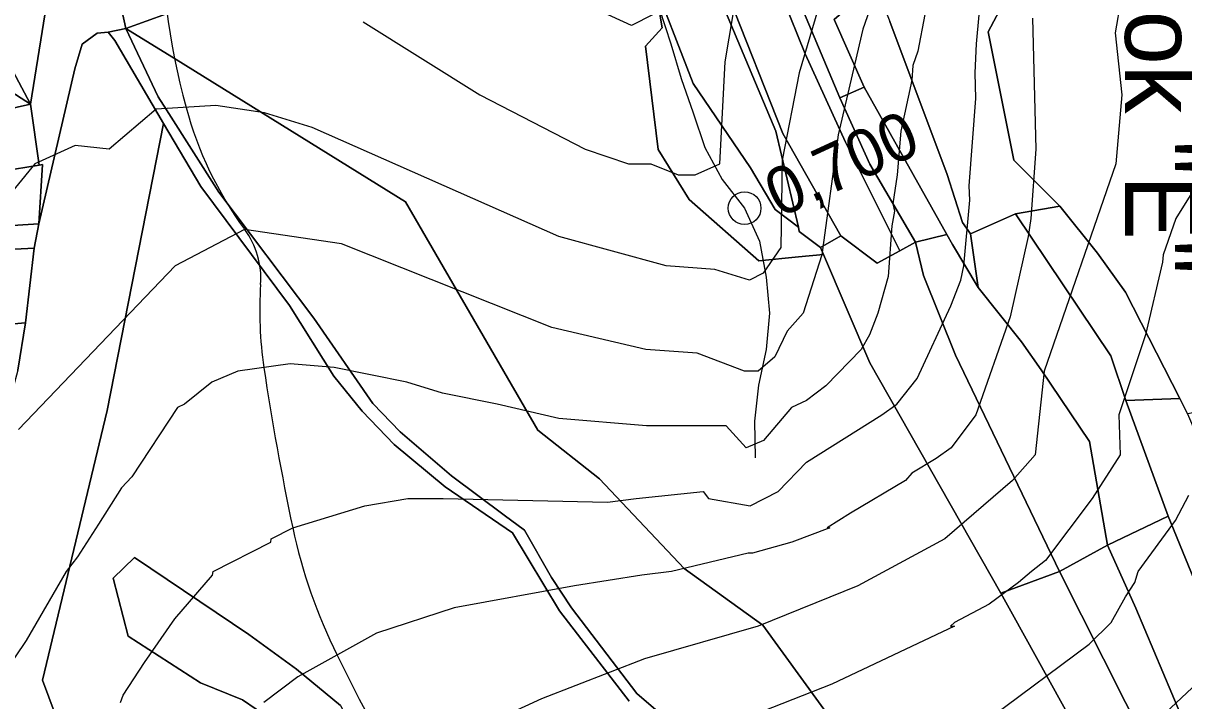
# Model space of a CAD drawing. Extents: x -510989 to -501240, y -1184665 to -1176098.
# Drawn here: x -504613.7 to -504294.9, y -1182831.5 to -1182645.4 of the extents above; entities that cross this region are included whole.
import ezdxf

# ---------------------------------------------------------------- set-up
doc = ezdxf.new("R2010")
doc.units = 0
for name, color, linetype in [('lesni_pozemek', 7, 'Continuous'), ('NAVRH_rozvodnice', 7, 'Continuous'), ('orna_puda', 7, 'Continuous'), ('ostatni_plocha_x_neplodna_puda', 7, 'Continuous'), ('ostatni_plocha_x_ostatni_komunikace', 7, 'Continuous'), ('STAV_zaplavove_uzemi', 7, 'Continuous'), ('trasovani_toku', 7, 'Continuous'), ('trvaly_travni_porost', 7, 'Continuous'), ('vrstevnice_01', 7, 'Continuous'), ('vrstevnice_02', 7, 'Continuous')]:
    doc.layers.add(name, color=color, linetype=linetype)

msp = doc.modelspace()

# ---------------------------------------------------------------- linework, layer by layer
at = {"layer": 'lesni_pozemek'}
for points in [[(-504108.08, -1182644.43), (-504125.54, -1182629.68), (-504155.94, -1182673.32), (-504174.32, -1182695.83), (-504210.52, -1182722.69), (-504235.93, -1182738.25), (-504264.25, -1182747.48), (-504293.81, -1182752.72), (-504295.93, -1182748.47), (-504310.85, -1182719.26), (-504318.59, -1182708.58), (-504328.95, -1182695.62), (-504341.55, -1182683.01), (-504348.64, -1182647.73), (-504338.72, -1182629.02), (-504335.18, -1182603.23), (-504338, -1182582.37), (-504351.89, -1182548.22), (-504366.04, -1182490.92), (-504369.86, -1182481.57), (-504383.74, -1182456.35), (-504376.66, -1182443.95), (-504372.24, -1182440.22)], [(-504338.72, -1182629.02), (-504348.64, -1182647.73), (-504341.55, -1182683.01), (-504328.95, -1182695.62), (-504341.13, -1182697.77), (-504353.45, -1182703.22), (-504355.71, -1182700.13), (-504359.86, -1182686.91), (-504375.6, -1182644.92)], [(-504439.39, -1182639.55), (-504438.17, -1182646.67), (-504442.8, -1182651.66), (-504439.24, -1182680.04), (-504430.76, -1182693.84), (-504411.67, -1182710.63), (-504400.74, -1182709.57), (-504393.85, -1182708.89), (-504381.11, -1182738.71), (-504345.16, -1182801.96), (-504341.93, -1182807.78), (-504298.15, -1182886.77)], [(-504331.17, -1182920.13), (-504410.51, -1182810.8), (-504432.14, -1182795.22), (-504455.44, -1182770.6), (-504472.39, -1182757.22), (-504508.71, -1182694.47), (-504571.7, -1182655.37), (-504585.52, -1182646.79), (-504568.82, -1182640.74)], [(-504599.72, -1182849.21), (-504608.48, -1182825.92), (-504590.64, -1182751.76), (-504575.15, -1182672.92), (-504564.97, -1182690.25), (-504540.58, -1182722.93), (-504528.43, -1182742.33), (-504520.61, -1182752), (-504511.86, -1182761.09), (-504497.83, -1182772.71), (-504479.34, -1182785.43), (-504466.36, -1182806.8), (-504447.26, -1182831.66)], [(-504526.58, -1182832.88), (-504538.67, -1182822.87), (-504551.79, -1182813.34), (-504583.14, -1182792.17), (-504589, -1182797.83), (-504584.94, -1182813.82), (-504565.01, -1182826.65), (-504553.49, -1182831.27), (-504549.73, -1182833.84)]]:
    msp.add_lwpolyline(points, dxfattribs=at)
for points in [[(-504484.36, -1182553.26), (-504470.6, -1182583.61), (-504463.9, -1182605.8), (-504441.71, -1182630.91), (-504429.65, -1182661.94), (-504413.93, -1182685.1), (-504407.11, -1182696.55), (-504400.77, -1182701.43), (-504400.5, -1182702.56), (-504394.66, -1182707), (-504393.85, -1182708.89), (-504400.74, -1182709.57), (-504411.67, -1182710.63), (-504430.76, -1182693.84), (-504439.24, -1182680.04), (-504442.8, -1182651.66), (-504438.17, -1182646.67), (-504439.39, -1182639.55), (-504465.08, -1182614.54), (-504471.59, -1182602.62), (-504478.43, -1182596.87), (-504482.37, -1182589.69), (-504481.12, -1182577.4), (-504492.36, -1182555.2)], [(-504585.52, -1182646.79), (-504571.7, -1182655.37), (-504508.71, -1182694.47), (-504472.39, -1182757.22), (-504455.44, -1182770.6), (-504432.14, -1182795.22), (-504410.51, -1182810.8), (-504331.17, -1182920.13), (-504365.5, -1182891.46), (-504398.97, -1182869.17), (-504445.16, -1182829.52), (-504463.11, -1182806.05), (-504468.63, -1182797.64), (-504475.97, -1182784.67), (-504481.61, -1182780.53), (-504496.11, -1182769.71), (-504510.14, -1182757.63), (-504517.71, -1182749.85), (-504533.93, -1182726.38), (-504560, -1182691.8), (-504574.41, -1182669.14), (-504576.68, -1182665.56)], [(-504341.13, -1182697.77), (-504328.95, -1182695.62), (-504318.59, -1182708.58), (-504310.85, -1182719.26), (-504295.93, -1182748.47), (-504310.8, -1182749.04), (-504314.92, -1182736.74)], [(-504341.13, -1182697.77), (-504314.92, -1182736.74), (-504310.8, -1182749.04), (-504299.12, -1182780.84), (-504315.84, -1182788.78), (-504320.73, -1182760.26), (-504334.05, -1182740.56), (-504339.43, -1182732.91), (-504351.37, -1182717.96), (-504353.45, -1182703.22)], [(-504368.55, -1182705.56), (-504359.99, -1182703.4), (-504358.45, -1182706.15), (-504351.37, -1182717.96), (-504339.43, -1182732.91), (-504334.05, -1182740.56), (-504320.73, -1182760.26), (-504315.84, -1182788.78), (-504329.01, -1182796.01), (-504357.58, -1182736.53), (-504366.36, -1182714.7)], [(-504589, -1182797.83), (-504583.14, -1182792.17), (-504551.79, -1182813.34), (-504538.67, -1182822.87), (-504526.58, -1182832.88), (-504516.79, -1182851.72), (-504488.95, -1182890.19), (-504496.5, -1182892.54), (-504526.79, -1182855.38), (-504540.95, -1182840.36), (-504549.73, -1182833.84), (-504553.49, -1182831.27), (-504565.01, -1182826.65), (-504584.94, -1182813.82)]]:
    msp.add_lwpolyline(points, close=True, dxfattribs=at)
at = {"layer": 'NAVRH_rozvodnice'}
for centre, radius, start, end in [((-504365.5, -1182613.94), 210.69, 180.0167, 195.009), ((-504471.89, -1182642.46), 100.54, 195.009, 216.3106), ((-504571.39, -1182715.58), 22.94, 356.0559, 36.3106), ((-504442.83, -1182724.45), 105.93, 176.0559, 188.4422), ((-503829.42, -1182633.41), 726.05, 188.44219, 191.9708), ((-504395.61, -1182753.45), 147.28, 191.9708, 206.4269), ((-503520.82, -1182318.69), 1124.15, 206.42689, 210.10212)]:
    msp.add_arc(centre, radius, start, end, dxfattribs=at)
at = {"layer": 'orna_puda'}
for points in [[(-504628.48, -1182645.79), (-504618.4, -1182663.31), (-504611.77, -1182667.61), (-504642.34, -1182674.45), (-504667.79, -1182680.12), (-504671.74, -1182655.56)], [(-504642.34, -1182674.45), (-504611.77, -1182667.61), (-504609.38, -1182684.36), (-504639.94, -1182689.35)], [(-504664.63, -1182703.93), (-504609.45, -1182700.52), (-504610.7, -1182707.2), (-504663.97, -1182709.93)], [(-504662.47, -1182731.93), (-504613.08, -1182727.66), (-504615.26, -1182740.69), (-504617.46, -1182749.23), (-504620.21, -1182760.83), (-504659.96, -1182762.59)]]:
    msp.add_lwpolyline(points, close=True, dxfattribs=at)
at = {"layer": 'ostatni_plocha_x_neplodna_puda'}
msp.add_lwpolyline([(-504630.43, -1182488.04), (-504608.32, -1182618.85), (-504607.36, -1182640.23), (-504611.77, -1182667.61), (-504623.06, -1182646.35)], dxfattribs=at)
for points in [[(-504458.37, -1182546.96), (-504454.38, -1182543.14), (-504451.31, -1182553.99), (-504437.74, -1182594.84), (-504423.71, -1182628.8), (-504419.99, -1182637.8), (-504405.05, -1182675.65), (-504389.13, -1182703.75), (-504394.66, -1182707), (-504400.5, -1182702.56), (-504400.77, -1182701.43), (-504407, -1182675), (-504442.08, -1182591.33), (-504450.57, -1182563.65)], [(-504394.66, -1182707), (-504389.13, -1182703.75), (-504379.11, -1182711.25), (-504372.88, -1182707.9), (-504368.55, -1182705.56), (-504366.36, -1182714.7), (-504357.58, -1182736.53), (-504329.01, -1182796.01), (-504345.16, -1182801.96), (-504381.11, -1182738.71), (-504393.85, -1182708.89)]]:
    msp.add_lwpolyline(points, close=True, dxfattribs=at)
at = {"layer": 'ostatni_plocha_x_ostatni_komunikace'}
for points in [[(-504618.04, -1182497.86), (-504608.41, -1182541.97), (-504603.34, -1182565.18), (-504598.85, -1182585.72), (-504593.32, -1182611.07), (-504585.52, -1182646.79), (-504590.37, -1182647.84), (-504593.41, -1182648.12), (-504597.52, -1182651.15), (-504599.57, -1182657.86), (-504609.45, -1182700.52), (-504608.44, -1182684.21), (-504609.38, -1182684.36), (-504611.77, -1182667.61), (-504607.36, -1182640.23), (-504608.32, -1182618.85), (-504630.43, -1182488.04)], [(-504615.26, -1182740.69), (-504613.08, -1182727.66), (-504610.7, -1182707.2), (-504609.45, -1182700.52), (-504599.57, -1182657.86), (-504597.52, -1182651.15), (-504593.41, -1182648.12), (-504590.37, -1182647.84), (-504588.53, -1182650.14), (-504575.15, -1182672.92), (-504590.64, -1182751.76), (-504608.48, -1182825.92), (-504599.72, -1182849.21), (-504577.81, -1182854.21), (-504550.94, -1182892.74), (-504564.43, -1182890.78), (-504566.03, -1182890.55), (-504580.83, -1182865.24), (-504608.94, -1182852.85), (-504612.96, -1182855.54), (-504612.11, -1182873.57), (-504616.89, -1182868.86)], [(-504447.26, -1182831.66), (-504466.36, -1182806.8), (-504479.34, -1182785.43), (-504497.83, -1182772.71), (-504511.86, -1182761.09), (-504520.61, -1182752), (-504528.43, -1182742.33), (-504540.58, -1182722.93), (-504564.97, -1182690.25), (-504575.15, -1182672.92), (-504588.53, -1182650.14), (-504590.37, -1182647.84), (-504585.52, -1182646.79), (-504576.68, -1182665.56), (-504574.41, -1182669.14), (-504560, -1182691.8), (-504533.93, -1182726.38), (-504517.71, -1182749.85), (-504510.14, -1182757.63), (-504496.11, -1182769.71), (-504481.61, -1182780.53), (-504475.97, -1182784.67), (-504468.63, -1182797.64), (-504463.11, -1182806.05), (-504445.16, -1182829.52), (-504398.97, -1182869.17)]]:
    msp.add_lwpolyline(points, dxfattribs=at)
at = {"layer": 'STAV_zaplavove_uzemi'}
msp.add_spline([(-502250.32, -1184002.61), (-502355.07, -1183875.41), (-502442.37, -1183790.61), (-502477.29, -1183700.82), (-502532.16, -1183578.61), (-502567.08, -1183448.91), (-502626.05, -1183402.34), (-502705.41, -1183380.59), (-502814.2, -1183349.87), (-502882.03, -1183297.39), (-502931.95, -1183237.24), (-503042.02, -1183107.97), (-503139.64, -1183018.94), (-503222.14, -1182957.59), (-503308.56, -1182839.96), (-503316.24, -1182784.92), (-503330.32, -1182756.77), (-503348.24, -1182719.65), (-503334.16, -1182651.82), (-503323.92, -1182595.5), (-503313.68, -1182526.39), (-503294.1, -1182480.5), (-503251.86, -1182396.03), (-503229.34, -1182314.37), (-503216.1, -1182227.15), (-503242.43, -1182174.5), (-503271.86, -1182129.59), (-503287.34, -1182081.58), (-503343.88, -1182028.1), (-503361.79, -1182008.91), (-503396.35, -1181952.59), (-503442.43, -1181933.39), (-503497.46, -1181888.6), (-503525.62, -1181860.44), (-503528.18, -1181837.4), (-503548.66, -1181767.01), (-503558.9, -1181729.89), (-503576.82, -1181682.53), (-503578.1, -1181621.1), (-503567.86, -1181572.46), (-503552.5, -1181536.63), (-503538.04, -1181458.36), (-503518.33, -1181411.9), (-503509.88, -1181341.51), (-503497.21, -1181207.63), (-503499.77, -1181097.56), (-503498.02, -1181031.35), (-503510.82, -1180970.85), (-503549.22, -1180952.23), (-503571.32, -1180940.6), (-503605.07, -1180937.11), (-503651.61, -1180939.44), (-503671.39, -1180917.33), (-503679.53, -1180892.89), (-503713.27, -1180871.95), (-503727.24, -1180859.15), (-503734.22, -1180833.55), (-503728.4, -1180799.81), (-503741.2, -1180770.72), (-503722.82, -1180725.17), (-503721.54, -1180703.41), (-503731.78, -1180697.01), (-503767.61, -1180699.57), (-503790.65, -1180697.01), (-503817.53, -1180697.01), (-503861.04, -1180686.77), (-503889.2, -1180675.25), (-503900.72, -1180668.85), (-503953.2, -1180679.09), (-503997.99, -1180697.01), (-504063.27, -1180722.61), (-504109.34, -1180749.49), (-504142.62, -1180776.36), (-504177.18, -1180796.84), (-504211.73, -1180817.32), (-504414.98, -1180961.5), (-504472.7, -1180998.11), (-504544.51, -1181068.5), (-504600.82, -1181143.12), (-504621.94, -1181196.62), (-504641.65, -1181267.01), (-504660.25, -1181350.62), (-504634.7, -1181398.32), (-504617.66, -1181447.72), (-504600.62, -1181492.01), (-504587, -1181548.23), (-504592.11, -1181628.29), (-504569.96, -1181682.81), (-504568.26, -1181664.07), (-504554.63, -1181621.48), (-504547.82, -1181597.63)], degree=3, dxfattribs=at)
at = {"layer": 'trasovani_toku'}
for p, q in [((-504438.89, -1182641.48), (-504435.82, -1182651)), ((-504435.82, -1182651), (-504432.98, -1182660.59)), ((-504432.98, -1182660.59), (-504429.66, -1182670.02)), ((-504429.66, -1182670.02), (-504426.48, -1182679.5)), ((-504426.48, -1182679.5), (-504421.71, -1182688.29)), ((-504421.71, -1182688.29), (-504415.54, -1182696.16)), ((-504415.54, -1182696.16), (-504411.45, -1182705.28)), ((-504411.45, -1182705.28), (-504409.58, -1182715.11)), ((-504409.58, -1182715.11), (-504408.7, -1182725.07)), ((-504408.7, -1182725.07), (-504409.64, -1182735.03)), ((-504409.64, -1182735.03), (-504411.74, -1182744.8)), ((-504411.74, -1182744.8), (-504412.78, -1182754.75)), ((-504412.78, -1182754.75), (-504412.66, -1182764.75))]:
    msp.add_line(p, q, dxfattribs=at)
msp.add_circle((-504415.54, -1182696.16), 4.5, dxfattribs=at)
at = {"layer": 'trvaly_travni_porost'}
for points in [[(-504431.39, -1182514.49), (-504417.38, -1182548.88), (-504411.65, -1182568.34), (-504398.82, -1182596.13), (-504384.22, -1182638.5), (-504390.96, -1182644.3), (-504382.71, -1182662.94), (-504389.35, -1182665.82), (-504402.24, -1182635.07), (-504406.52, -1182621.24), (-504399.61, -1182618.2), (-504439.4, -1182518.12)], [(-504429.03, -1182513.42), (-504414.39, -1182547.28), (-504398.36, -1182588.59), (-504375.6, -1182644.92), (-504359.86, -1182686.91), (-504355.71, -1182700.13), (-504353.45, -1182703.22), (-504351.37, -1182717.96), (-504358.45, -1182706.15), (-504359.99, -1182703.4), (-504382.71, -1182662.94), (-504390.96, -1182644.3), (-504384.22, -1182638.5), (-504398.82, -1182596.13), (-504411.65, -1182568.34), (-504417.38, -1182548.88), (-504431.39, -1182514.49)], [(-504469.74, -1182549.81), (-504458.37, -1182546.96), (-504450.57, -1182563.65), (-504442.08, -1182591.33), (-504407, -1182675), (-504400.77, -1182701.43), (-504407.11, -1182696.55), (-504413.93, -1182685.1), (-504429.65, -1182661.94), (-504441.71, -1182630.91), (-504463.9, -1182605.8), (-504470.6, -1182583.61), (-504484.36, -1182553.26)], [(-504689.61, -1182599.16), (-504691.82, -1182578.53), (-504672.23, -1182604), (-504646, -1182610.56), (-504636.51, -1182617.7), (-504623.06, -1182646.35), (-504611.77, -1182667.61), (-504618.4, -1182663.31), (-504628.48, -1182645.79), (-504671.74, -1182655.56), (-504674.38, -1182656.17), (-504677.82, -1182627.01), (-504680.21, -1182618.25), (-504682.2, -1182609.48), (-504683.4, -1182606.3)], [(-504593.32, -1182611.07), (-504528.72, -1182594.2), (-504522.2, -1182623.85), (-504568.82, -1182640.74), (-504585.52, -1182646.79)], [(-504411.14, -1182623.27), (-504398.86, -1182653.8), (-504387.81, -1182678.08), (-504372.88, -1182707.9), (-504379.11, -1182711.25), (-504389.13, -1182703.75), (-504405.05, -1182675.65), (-504419.99, -1182637.8), (-504423.71, -1182628.8)], [(-504406.52, -1182621.24), (-504402.24, -1182635.07), (-504389.35, -1182665.82), (-504381.13, -1182684.09), (-504368.55, -1182705.56), (-504372.88, -1182707.9), (-504387.81, -1182678.08), (-504398.86, -1182653.8), (-504411.14, -1182623.27)], [(-504389.35, -1182665.82), (-504382.71, -1182662.94), (-504359.99, -1182703.4), (-504368.55, -1182705.56), (-504381.13, -1182684.09)], [(-504608.44, -1182684.21), (-504609.45, -1182700.52), (-504664.63, -1182703.93), (-504665.5, -1182693.52), (-504639.94, -1182689.35), (-504609.38, -1182684.36)], [(-504610.7, -1182707.2), (-504613.08, -1182727.66), (-504662.47, -1182731.93), (-504663.97, -1182709.93)], [(-504295.93, -1182748.47), (-504293.81, -1182752.72), (-504270.73, -1182806.86), (-504242.32, -1182864.99), (-504257.2, -1182871.75), (-504275.32, -1182839), (-504299.12, -1182780.84), (-504310.8, -1182749.04)], [(-504299.12, -1182780.84), (-504275.32, -1182839), (-504257.2, -1182871.75), (-504274.24, -1182874.7), (-504286.34, -1182851.87), (-504290.77, -1182847.15), (-504308.05, -1182806.06), (-504315.84, -1182788.78)], [(-504315.84, -1182788.78), (-504308.05, -1182806.06), (-504290.77, -1182847.15), (-504286.34, -1182851.87), (-504274.24, -1182874.7), (-504277.6, -1182876.13), (-504285.12, -1182880.67), (-504298.81, -1182856.06), (-504329.01, -1182796.01)], [(-504329.01, -1182796.01), (-504298.81, -1182856.06), (-504285.12, -1182880.67), (-504298.15, -1182886.77), (-504341.93, -1182807.78), (-504345.16, -1182801.96)]]:
    msp.add_lwpolyline(points, close=True, dxfattribs=at)
at = {"layer": 'vrstevnice_01'}
for points in [[(-504345.69, -1182477), (-504369.91, -1182528), (-504376, -1182553), (-504382.5, -1182598), (-504400.5, -1182659), (-504405.19, -1182683), (-504405.59, -1182707), (-504410.41, -1182714), (-504414.19, -1182716), (-504423.69, -1182713), (-504437.09, -1182712), (-504466.59, -1182704), (-504534.31, -1182674), (-504547.41, -1182670), (-504560.81, -1182668), (-504577.19, -1182669), (-504590.09, -1182680), (-504599.5, -1182679), (-504610.59, -1182684), (-504631.09, -1182709)], [(-504366, -1182643), (-504367.91, -1182653), (-504369.31, -1182657), (-504369.59, -1182661), (-504372.59, -1182675), (-504373.59, -1182687), (-504374.81, -1182695), (-504374.31, -1182697), (-504375.09, -1182701), (-504376.09, -1182715), (-504378.91, -1182725), (-504381.19, -1182731), (-504383.5, -1182735), (-504393.19, -1182745), (-504398.5, -1182749), (-504402.69, -1182751), (-504410.31, -1182760), (-504415.09, -1182762), (-504420.59, -1182756), (-504430.31, -1182756), (-504442.5, -1182756), (-504466.59, -1182754), (-504483.5, -1182750), (-504498.5, -1182747), (-504508.31, -1182744), (-504528.31, -1182740), (-504540.41, -1182739), (-504554.81, -1182741), (-504561.91, -1182744), (-504569.41, -1182750), (-504571.31, -1182751), (-504583.91, -1182770), (-504586.69, -1182773), (-504593.09, -1182783), (-504598.81, -1182792), (-504601.91, -1182796), (-504612.91, -1182815), (-504619, -1182824)], [(-504440.69, -1182643), (-504446.59, -1182646), (-504457.41, -1182641)], [(-504336.41, -1182644), (-504335.5, -1182680), (-504336.91, -1182699), (-504337.59, -1182704), (-504342.59, -1182726), (-504352, -1182753), (-504358.81, -1182762), (-504362.91, -1182765), (-504369.59, -1182769), (-504371.31, -1182771), (-504386.41, -1182780), (-504392.81, -1182784), (-504392.09, -1182784), (-504402.59, -1182788), (-504413.41, -1182791), (-504414.59, -1182791), (-504435.59, -1182796), (-504443.81, -1182797), (-504462.31, -1182800), (-504495.31, -1182806), (-504516.69, -1182813), (-504538.31, -1182825), (-504547.59, -1182832)], [(-504292.69, -1182692), (-504297.09, -1182699), (-504300.5, -1182709), (-504300.69, -1182711), (-504305.41, -1182731), (-504312.69, -1182753), (-504312.31, -1182764), (-504320, -1182776), (-504332.91, -1182793), (-504336.69, -1182796), (-504340.31, -1182799), (-504348.31, -1182805), (-504357.91, -1182810), (-504359, -1182811), (-504357.91, -1182811), (-504391.59, -1182827), (-504432.31, -1182843)], [(-504308.59, -1182843), (-504292.59, -1182828)]]:
    msp.add_lwpolyline(points, dxfattribs=at)
at = {"layer": 'vrstevnice_02'}
for points in [[(-504297.59, -1182409), (-504312.19, -1182443), (-504329.69, -1182490), (-504336, -1182504), (-504352.31, -1182535), (-504359.59, -1182557), (-504365.81, -1182594), (-504369, -1182607), (-504383.09, -1182647), (-504389.81, -1182676), (-504394.31, -1182709), (-504399.41, -1182725), (-504403.81, -1182730), (-504407.19, -1182737), (-504411.81, -1182741), (-504415.59, -1182741), (-504428.59, -1182736), (-504442.69, -1182735), (-504468.5, -1182729), (-504526.31, -1182706), (-504552.91, -1182702), (-504572, -1182712), (-504615, -1182757)], [(-504121.31, -1182463), (-504139.91, -1182478), (-504152.81, -1182485), (-504162.31, -1182489), (-504187, -1182492), (-504211.5, -1182491), (-504223.5, -1182493), (-504237.41, -1182501), (-504256.09, -1182533), (-504278.09, -1182561), (-504306, -1182619), (-504310.59, -1182630), (-504313.69, -1182648), (-504311.91, -1182665), (-504313.5, -1182684), (-504333.19, -1182741), (-504335.69, -1182764)], [(-504587, -1182832), (-504586.31, -1182830), (-504580.41, -1182821), (-504572.09, -1182809), (-504561.69, -1182797), (-504561.59, -1182796), (-504545.69, -1182788), (-504545.59, -1182787), (-504539.69, -1182784), (-504519.91, -1182778), (-504508.09, -1182776), (-504498.31, -1182776), (-504453.19, -1182777), (-504445.31, -1182776), (-504426.91, -1182774), (-504425.41, -1182776), (-504414, -1182778), (-504406.31, -1182774), (-504398.5, -1182766), (-504377.81, -1182753), (-504373.69, -1182750), (-504368.09, -1182743), (-504358.91, -1182723), (-504356.09, -1182716), (-504355.31, -1182712), (-504353.69, -1182694), (-504353.81, -1182690), (-504352, -1182666), (-504352.19, -1182659), (-504351.81, -1182651), (-504350.31, -1182634)], [(-504520.31, -1182645), (-504488.31, -1182665), (-504459.31, -1182680), (-504447.41, -1182684), (-504441.31, -1182684), (-504433.81, -1182687), (-504429.09, -1182687), (-504422.31, -1182684), (-504420.91, -1182656), (-504418.69, -1182643)], [(-504335.69, -1182764), (-504341.91, -1182771), (-504360.5, -1182787), (-504384.41, -1182800), (-504411.81, -1182811), (-504443, -1182820), (-504471.31, -1182831), (-504490.81, -1182840)], [(-504347.69, -1182836), (-504320.91, -1182816), (-504314.81, -1182810), (-504310.91, -1182803), (-504308.31, -1182799), (-504307.41, -1182796), (-504297.19, -1182782), (-504293.5, -1182775)]]:
    msp.add_lwpolyline(points, dxfattribs=at)

# ---------------------------------------------------------------- texts
at = {"layer": 'NAVRH_rozvodnice'}
msp.add_text('přítok "E"', height=20, rotation=270, dxfattribs=at).set_placement((-504310.99, -1182603.25))
at = {"layer": 'trasovani_toku'}
msp.add_text('0,700', height=13, rotation=24.7843, dxfattribs=at).set_placement((-504405.95, -1182698.92))

doc.saveas('drawing.dxf')
